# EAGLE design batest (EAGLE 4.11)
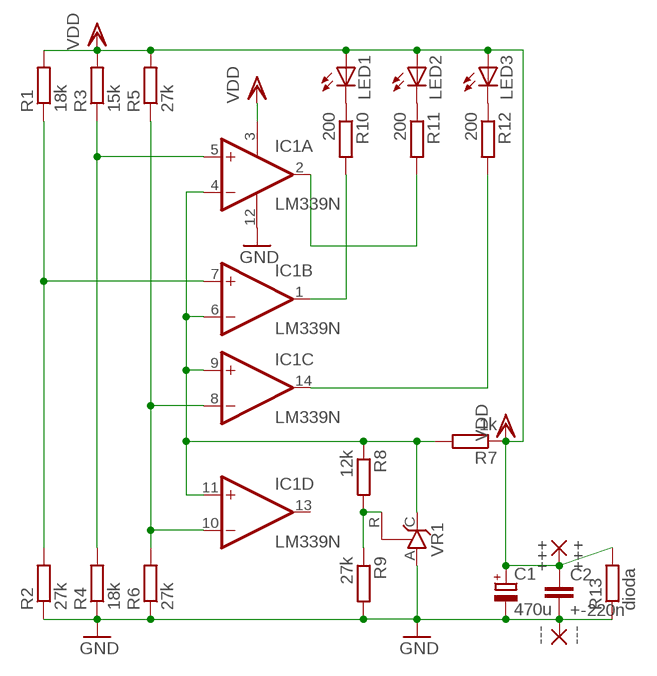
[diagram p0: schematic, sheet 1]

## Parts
+++  +++  3,17/1,3  [3,17/1,3]
---  ---  3,17/1,3  [3,17/1,3]
C1  470u  CPOL-EUE3.5-8  [E3,5-8]
C2  +-220n  C-EU050-024X044  [C050-024X044]
IC1  LM339N  [DIL14]
LED1  LED3MM  [LED3MM]
LED2  LED3MM  [LED3MM]
LED3  LED3MM  [LED3MM]
R1  18k  R-EU_0207/7  [0207/7]
R2  27k  R-EU_0207/7  [0207/7]
R3  15k  R-EU_0207/7  [0207/7]
R4  18k  R-EU_0207/7  [0207/7]
R5  27k  R-EU_0207/7  [0207/7]
R6  27k  R-EU_0207/7  [0207/7]
R7  1k  R-EU_0207/7  [0207/7]
R8  12k  R-EU_0207/7  [0207/7]
R9  27k  R-EU_0207/7  [0207/7]
R10  200  R-EU_0207/7  [0207/7]
R11  200  R-EU_0207/7  [0207/7]
R12  200  R-EU_0207/7  [0207/7]
R13  dioda  R-EU_0207/5V  [0207/5V]
VR1  TL431CLP  [TO92-CLP]

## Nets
GND: ---.1(P) C1.- C2.2 IC1.12(P:GND) R2.1 R4.1 R6.1 R9.2 R13.1 VR1.A
N$1: IC1.7(B:+IN) R1.1 R2.2
N$2: IC1.5(A:+IN) R3.1 R4.2
N$3: IC1.8(C:-IN) IC1.10(D:-IN) R5.1 R6.2
N$4: IC1.1(B:OUT) R10.2
N$6: R8.2 R9.1 VR1.R
N$7: IC1.2(A:OUT) R11.2
N$8: IC1.14(C:OUT) R12.2
N$9: LED1.K(C) R10.1
N$10: LED2.K(C) R11.1
N$11: LED3.K(C) R12.1
N$12: IC1.4(A:-IN) IC1.6(B:-IN) IC1.9(C:+IN) IC1.11(D:+IN) R7.2 R8.1 VR1.C
VDD: +++.1(P) C1.+ C2.1 IC1.3(P:V+) LED1.A LED2.A LED3.A R1.2 R3.2 R5.2 R7.1 R13.2
Unconnected: IC1.13(D:OUT)

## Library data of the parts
+++ --- = wirepad:3,17/1,3: THROUGH-HOLE PAD
C1 = rcl:CPOL-EU: POLARIZED CAPACITOR, European symbol
C2 = rcl:C-EU: CAPACITOR, European symbol
IC1 = linear:LM339: Low Power Low Offset Voltage Quad Comparators with open collector; LM139/LM239/LM339/LM2901/LM3302
LED1-LED3 = led:LED: LED
R1-R13 = rcl:R-EU_: RESISTOR, European symbol
VR1 = v-reg:TL431CLP: VOLTAGE REGULATOR

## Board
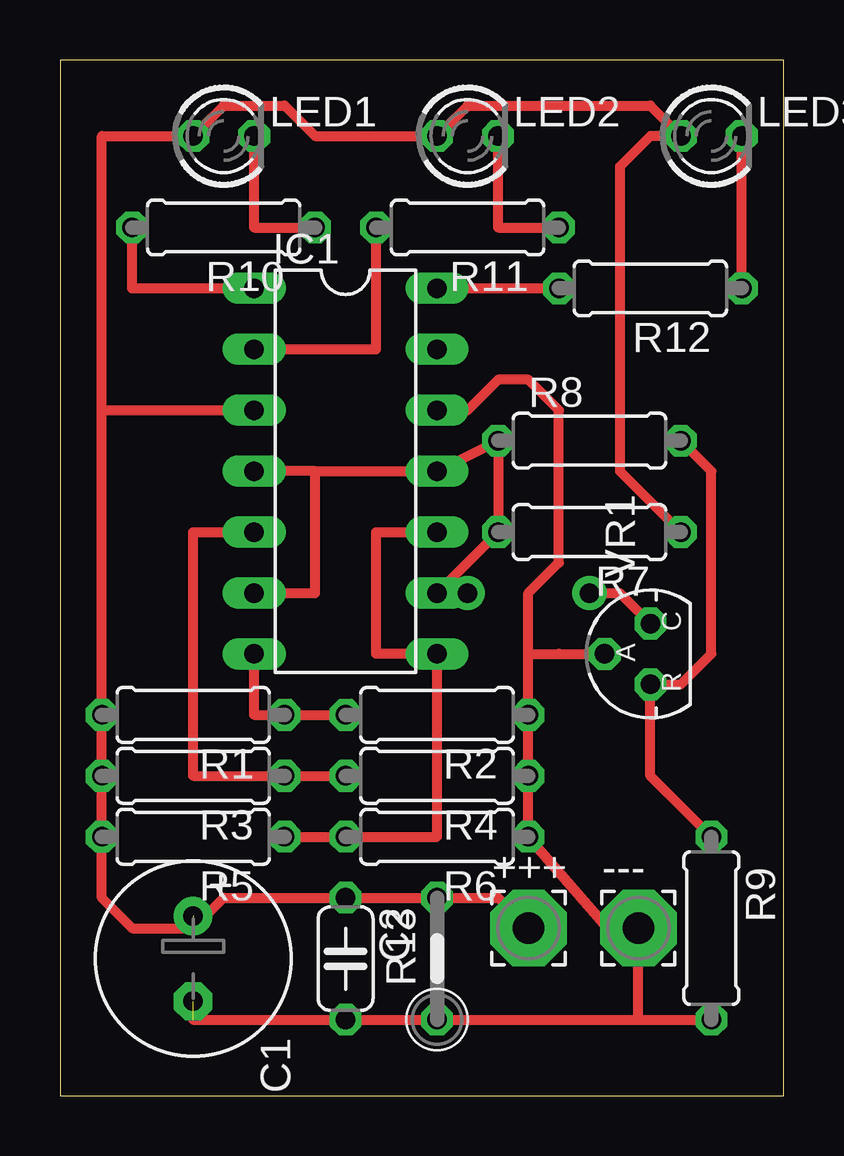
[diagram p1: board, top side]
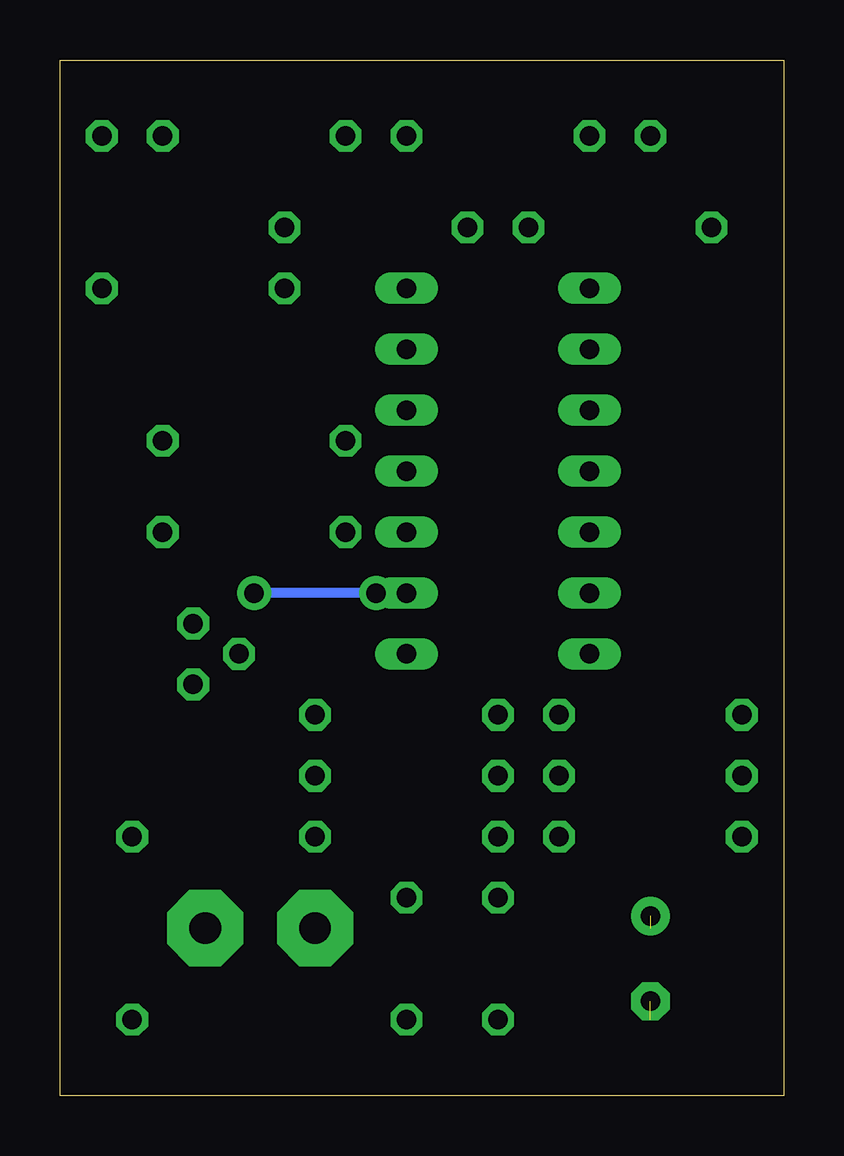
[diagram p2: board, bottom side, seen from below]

Size 30.15 x 43.17 mm. Coordinates in mm from the lower left corner, seen from the top.
Outline: 0,0 30.15,0 30.15,43.17 0,43.17 0,0
Copper layers (1*16): Top 0.035mm / dielectric 1.5mm / Bottom 0.035mm
Design rules "default": minimum track width 10mil, minimum drill 24mil, track to track 8mil, track to pad 8mil, pad to pad 8mil, via to via 8mil, smd to smd 8mil, copper to edge 40mil, drill to drill 8mil, minimum pad ring 10mil, minimum via ring 8mil, stop-mask expansion 4mil, vias tented up to drill 0mil, thermal gap 10mil

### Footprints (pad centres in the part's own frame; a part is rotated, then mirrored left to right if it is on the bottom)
3,17/1,3 = drill 1.321 pad 3.175 octagon: 1 0,0
E3,5-8 = drill 0.813 pad 1.6 round: + -1.778,0 | drill 0.813 pad 1.6 octagon: - 1.778,0
C050-024X044 = drill 0.813 octagon: 1 -2.54,0; 2 2.54,0
DIL14 = drill 0.813 long: 1 -7.62,-3.81; 2 -5.08,-3.81; 3 -2.54,-3.81; 4 0,-3.81; 5 2.54,-3.81; 6 5.08,-3.81; 7 7.62,-3.81; 8 7.62,3.81; 9 5.08,3.81; 10 2.54,3.81; 11 0,3.81; 12 -2.54,3.81; 13 -5.08,3.81; 14 -7.62,3.81
LED3MM = drill 0.813 octagon: A -1.27,0; K 1.27,0
0207/7 = drill 0.813 octagon: 1 -3.81,0; 2 3.81,0
0207/5V = drill 0.813 octagon: 1 -2.54,0; 2 2.54,0
TO92-CLP = drill 0.813 octagon: A 0,1.905; C 1.27,0; R -1.27,0

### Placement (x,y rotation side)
+++  19.52,6.98 0 top
---  24.1,6.98 0 top
C1  5.55,5.71 270 top
C2  11.9,5.71 270 top
IC1  11.9,26.03 270 top
LED1  6.82,40 0 top
LED2  16.98,40 0 top
LED3  27.14,40 0 top
R1  5.55,15.87 180 top
R2  15.71,15.87 180 top
R3  5.55,13.33 180 top
R4  15.71,13.33 180 top
R5  5.55,10.79 180 top
R6  15.71,10.79 180 top
R7  22.06,23.49 180 top
R8  22.06,27.3 0 top
R9  27.14,6.98 270 top
R10  6.82,36.19 180 top
R11  16.98,36.19 180 top
R12  24.6,33.65 180 top
R13  15.71,5.71 90 top
VR1  24.6,18.41 90 top

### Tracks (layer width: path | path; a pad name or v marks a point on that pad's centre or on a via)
GND  (1 unrouted)
  Top 0.406: 5.55,3.17 C2.2 R13.1 24.1,3.17 | 24.1,3.17 R9.2 | 19.52,18.41 R2.1 R4.1 R6.1 22.83,6.98 ---.1 24.1,3.17 | 19.52,18.41 20.79,18.41 | 20.79,18.41 22.06,18.41 | 20.79,18.41 VR1.A | 19.52,18.41 19.52,20.95 20.79,22.22 20.79,28.57 19.52,29.84 18.25,29.84 16.98,28.57 IC1.12
N$1
  Top 0.406: R2.2 R1.1 8.09,15.87 IC1.7
N$2
  Top 0.406: R4.2 R3.1 5.55,13.33 5.55,23.49 IC1.5
N$3
  Top 0.406: R5.1 R6.2 15.71,10.79 IC1.8 13.17,18.41 13.17,23.49 IC1.10
N$4
  Top 0.406: R10.2 3.01,33.65 IC1.1
N$6
  Top 0.406: R9.1 24.6,13.33 VR1.R 25.87,17.14 27.14,18.41 27.14,26.03 R8.2
N$7
  Top 0.406: R11.2 13.17,31.11 IC1.2
N$8
  Top 0.406: IC1.14 R12.2
N$9
  Top 0.406: LED1.K 8.09,36.19 R10.1
N$10
  Top 0.406: LED2.K 18.25,36.19 R11.1
N$11
  Top 0.406: R12.1 LED3.K
N$12  (via drill 0.81 pad 1.42)
  Top 0.406: IC1.6 10.63,20.95 10.63,26.03 | 10.63,26.03 IC1.4 | 10.63,26.03 IC1.11 R8.1 R7.2 IC1.9 v16.98,20.95 | v22.06,20.95 23.33,20.95 VR1.C
  Bottom 0.406: v16.98,20.95 v22.06,20.95
VDD  (1 unrouted)
  Top 0.406: 1.74,28.57 IC1.3 | 1.74,28.57 R1.2 R3.2 R5.2 1.74,8.25 3.01,6.98 5.55,6.98 6.82,8.25 C2.1 R13.2 18.25,8.25 +++.1 | 1.74,28.57 1.74,40 LED1.A 6.82,41.27 9.36,41.27 10.63,40 LED2.A 16.98,41.27 24.6,41.27 LED3.A 24.6,40 23.33,38.73 23.33,26.03 R7.1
